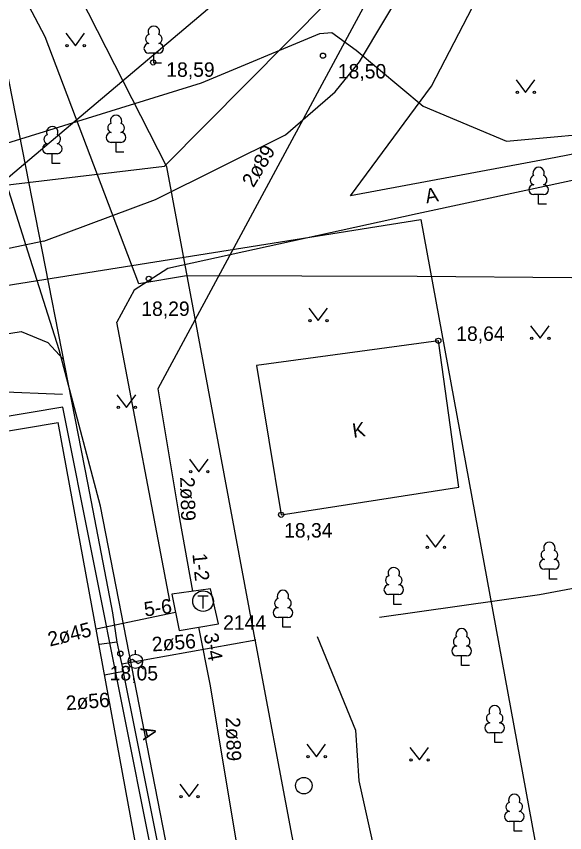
# Model space of a CAD drawing. Extents: x 713497 to 713863, y 6590062 to 6590327.
# Drawn here: x 713682.26 to 713708.83, y 6590102.5 to 6590142.1 of the extents above; entities that cross this region are included whole.
import ezdxf

# ---------------------------------------------------------------- set-up
doc = ezdxf.new("R2010")
doc.units = 0
for name, color, linetype in [('HALJASTUS', 7, 'Continuous'), ('HOONE', 7, 'Continuous'), ('HOONEDET', 7, 'Continuous'), ('KORGUS', 7, 'Continuous'), ('KTRASS', 7, 'Continuous'), ('MPKAABEL', 7, 'Continuous'), ('PUU', 7, 'Continuous'), ('SIKAEV', 7, 'Continuous'), ('SITRASS', 7, 'Continuous'), ('TEE', 7, 'Continuous'), ('TKAEV', 7, 'Continuous'), ('TORU NR', 7, 'Continuous'), ('TTRASS', 7, 'Continuous'), ('Слой 1', 7, 'Continuous')]:
    doc.layers.add(name, color=color, linetype=linetype)

msp = doc.modelspace()

# ---------------------------------------------------------------- linework, layer by layer
at = {"layer": 'HALJASTUS'}
for p, q in [((713684.657, 6590141.277), (713685.12, 6590140.67)), ((713685.12, 6590140.67), (713685.566, 6590141.277)), ((713706.477, 6590139.017), (713706.94, 6590138.41)), ((713706.94, 6590138.41), (713707.386, 6590139.017)), ((713696.427, 6590127.947), (713696.89, 6590127.34)), ((713696.89, 6590127.34), (713697.336, 6590127.947)), ((713707.177, 6590127.087), (713707.64, 6590126.48)), ((713707.64, 6590126.48), (713708.086, 6590127.087)), ((713687.137, 6590123.737), (713687.6, 6590123.13)), ((713687.6, 6590123.13), (713688.046, 6590123.737)), ((713690.647, 6590120.617), (713691.11, 6590120.01)), ((713691.11, 6590120.01), (713691.556, 6590120.617)), ((713702.117, 6590116.947), (713702.58, 6590116.34)), ((713702.58, 6590116.34), (713703.026, 6590116.947)), ((713696.337, 6590106.787), (713696.8, 6590106.18)), ((713696.8, 6590106.18), (713697.246, 6590106.787)), ((713701.327, 6590106.637), (713701.79, 6590106.03)), ((713701.79, 6590106.03), (713702.236, 6590106.637)), ((713690.177, 6590104.857), (713690.64, 6590104.25)), ((713690.64, 6590104.25), (713691.086, 6590104.857))]:
    msp.add_line(p, q, dxfattribs=at)
for points in [[(713712.88, 6590115.85), (713712.19, 6590114.89), (713707.62, 6590114.04), (713699.86, 6590112.93)], [(713696.83, 6590112.02), (713698.69, 6590107.47), (713698.85, 6590105.02), (713701.61, 6590092.64)]]:
    msp.add_lwpolyline(points, dxfattribs=at)
for centre, radius in [((713684.719, 6590140.67), 0.055), ((713685.548, 6590140.67), 0.055), ((713706.539, 6590138.41), 0.055), ((713707.368, 6590138.41), 0.055), ((713696.489, 6590127.34), 0.055), ((713697.318, 6590127.34), 0.055), ((713707.239, 6590126.48), 0.055), ((713708.068, 6590126.48), 0.055), ((713687.199, 6590123.13), 0.055), ((713688.028, 6590123.13), 0.055), ((713690.709, 6590120.01), 0.055), ((713691.538, 6590120.01), 0.055), ((713702.179, 6590116.34), 0.055), ((713703.008, 6590116.34), 0.055), ((713696.399, 6590106.18), 0.055), ((713697.228, 6590106.18), 0.055), ((713701.389, 6590106.03), 0.055), ((713702.218, 6590106.03), 0.055), ((713696.19, 6590104.78), 0.4), ((713690.239, 6590104.25), 0.055), ((713691.068, 6590104.25), 0.055)]:
    msp.add_circle(centre, radius, dxfattribs=at)
at = {"layer": 'HOONE'}
for p, q in [((713688.03, 6590111.16), (713688.03, 6590111.357)), ((713687.68, 6590110.808), (713687.891, 6590110.914)), ((713687.891, 6590110.914), (713688.169, 6590110.706)), ((713687.783, 6590110.563), (713687.643, 6590110.423)), ((713688.169, 6590110.706), (713688.38, 6590110.812)), ((713688.277, 6590110.563), (713688.417, 6590110.423))]:
    msp.add_line(p, q, dxfattribs=at)
for points in [[(713734.713, 6590179.152), (713722.026, 6590168.127), (713722.157, 6590168.056), (713711.65, 6590159.35), (713701.26, 6590150.68), (713673.462, 6590127.187), (713672.85, 6590126.67), (713647.99, 6590122.51), (713633.578, 6590120.32)], [(713693.84, 6590111.86), (713689.55, 6590134.79), (713682.39, 6590148.87), (713677.2, 6590159.52), (713676.53, 6590160.46), (713675.86, 6590163.24), (713675.04, 6590167.62)], [(713665.89, 6590132.03), (713669.505, 6590132.457), (713689.44, 6590134.83), (713709.36, 6590154.95), (713711.89, 6590153.81)], [(713693.89, 6590125.16), (713695.09, 6590117.91), (713703.71, 6590119.26), (713702.71, 6590126.36), (713693.89, 6590125.16)], [(713688.394, 6590100.066), (713671.828, 6590096.986), (713667.863, 6590119.623), (713684.288, 6590122.388)], [(713688.35, 6590100.23), (713684.288, 6590122.388)], [(713687.37, 6590110.69), (713693.86, 6590111.86)], [(713701.75, 6590069.87), (713695.62, 6590102.33), (713693.84, 6590111.87)]]:
    msp.add_lwpolyline(points, dxfattribs=at)
msp.add_circle((713688.03, 6590110.81), 0.35, dxfattribs=at)
at = {"layer": 'HOONEDET'}
for points in [[(713667.208, 6590120.227), (713671.415, 6590096.203), (713682.109, 6590098.012), (713685.75, 6590098.67), (713689.49, 6590099.42), (713688.82, 6590101.51), (713684.52, 6590123.14), (713667.208, 6590120.227)], [(713686.539, 6590110.153), (713687.45, 6590110.33), (713687.15, 6590111.74), (713686.268, 6590111.626)]]:
    msp.add_lwpolyline(points, dxfattribs=at)
at = {"layer": 'KORGUS'}
for centre in [(713697.12, 6590140.19), (713688.89, 6590139.86), (713688.68, 6590129.37), (713702.71, 6590126.36), (713695.09, 6590117.92), (713687.3, 6590111.18)]:
    msp.add_circle(centre, 0.125, dxfattribs=at)
at = {"layer": 'KTRASS'}
msp.add_line((713674.505, 6590124.158), (713684.495, 6590123.77), dxfattribs=at)
at = {"layer": 'MPKAABEL'}
for points in [[(713648.898, 6590189.999), (713650.232, 6590187.386), (713653.619, 6590186.331), (713654.135, 6590185.833), (713654.6, 6590184.884), (713659.445, 6590156.75), (713659.718, 6590154.881), (713660.539, 6590151.792), (713660.839, 6590151.655), (713663.967, 6590152.428), (713664.337, 6590151.977), (713669.307, 6590132.418), (713669.804, 6590132.227), (713691.237, 6590138.869), (713696.964, 6590141.27), (713697.553, 6590141.309), (713698.727, 6590140.465), (713701.978, 6590137.747), (713706.02, 6590136.037), (713711.684, 6590136.564)], [(713695.67, 6590069.59), (713692.27, 6590087.9), (713686.34, 6590118.33), (713684.33, 6590125.92), (713682.83, 6590130.66), (713676.1, 6590152.02), (713674.73, 6590155.85), (713674.34, 6590157.36), (713673.46, 6590161.22), (713670.72, 6590177.53), (713669.67, 6590183.54), (713667.81, 6590183.17)], [(713712.95, 6590130.05), (713709.16, 6590129.42), (713701.69, 6590129.47), (713690.5, 6590129.51), (713688.19, 6590129.12), (713683.66, 6590141.1), (713679.81, 6590148.4), (713679.37, 6590149.39), (713679.04, 6590150.26), (713678.83, 6590150.79), (713678.48, 6590151.44), (713677.98, 6590152.02), (713677.43, 6590152.31), (713676.95, 6590152.28), (713676.524, 6590152.014), (713670.183, 6590149.934), (713666.077, 6590148.723), (713655.565, 6590146.628), (713640.392, 6590143.766), (713637.411, 6590156.292), (713634.246, 6590158.892), (713632.822, 6590162.256), (713631.92, 6590167.25), (713628.288, 6590166.652)]]:
    msp.add_lwpolyline(points, dxfattribs=at)
at = {"layer": 'PUU'}
for p, q in [((713689.16, 6590140.305), (713688.68, 6590140.305)), ((713688.92, 6590139.83), (713688.92, 6590140.305)), ((713689.3, 6590139.83), (713688.92, 6590139.83)), ((713687.33, 6590135.985), (713686.85, 6590135.985)), ((713687.09, 6590135.51), (713687.09, 6590135.985)), ((713684.24, 6590135.435), (713683.76, 6590135.435)), ((713684, 6590134.96), (713684, 6590135.435)), ((713687.47, 6590135.51), (713687.09, 6590135.51)), ((713684.38, 6590134.96), (713684, 6590134.96)), ((713707.81, 6590133.455), (713707.33, 6590133.455)), ((713707.57, 6590132.98), (713707.57, 6590133.455)), ((713707.95, 6590132.98), (713707.57, 6590132.98)), ((713708.33, 6590115.275), (713707.85, 6590115.275)), ((713708.09, 6590114.8), (713708.09, 6590115.275)), ((713708.47, 6590114.8), (713708.09, 6590114.8)), ((713700.79, 6590114.045), (713700.31, 6590114.045)), ((713700.55, 6590113.57), (713700.55, 6590114.045)), ((713700.93, 6590113.57), (713700.55, 6590113.57)), ((713695.42, 6590112.935), (713694.94, 6590112.935)), ((713695.18, 6590112.46), (713695.18, 6590112.935)), ((713695.56, 6590112.46), (713695.18, 6590112.46)), ((713704.08, 6590111.075), (713703.6, 6590111.075)), ((713703.84, 6590110.6), (713703.84, 6590111.075)), ((713704.22, 6590110.6), (713703.84, 6590110.6)), ((713705.68, 6590107.345), (713705.2, 6590107.345)), ((713705.44, 6590106.87), (713705.44, 6590107.345)), ((713705.82, 6590106.87), (713705.44, 6590106.87)), ((713706.63, 6590103.045), (713706.15, 6590103.045)), ((713706.39, 6590102.57), (713706.39, 6590103.045)), ((713706.77, 6590102.57), (713706.39, 6590102.57))]:
    msp.add_line(p, q, dxfattribs=at)
for centre, radius, start, end in [((713688.92, 6590141.35), 0.277, 332.5799, 207.4201), ((713688.75, 6590141.003), 0.233, 109.0217, 253.1415), ((713689.09, 6590141.003), 0.233, 286.8508, 70.9859), ((713688.683, 6590140.542), 0.238, 90.0016, 269.3953), ((713689.157, 6590140.542), 0.238, 270.6047, 89.9984), ((713687.09, 6590137.03), 0.277, 332.5799, 207.4201), ((713684, 6590136.48), 0.277, 332.5799, 207.4201), ((713686.92, 6590136.683), 0.233, 109.0217, 253.1415), ((713687.26, 6590136.683), 0.233, 286.8508, 70.9859), ((713683.83, 6590136.133), 0.233, 109.0217, 253.1415), ((713684.17, 6590136.133), 0.233, 286.8508, 70.9859), ((713686.853, 6590136.222), 0.238, 90.0016, 269.3953), ((713687.327, 6590136.222), 0.238, 270.6047, 89.9984), ((713683.763, 6590135.672), 0.238, 90.0016, 269.3953), ((713684.237, 6590135.672), 0.238, 270.6047, 89.9984), ((713707.57, 6590134.5), 0.277, 332.5799, 207.4201), ((713707.4, 6590134.153), 0.233, 109.0217, 253.1415), ((713707.74, 6590134.153), 0.233, 286.8508, 70.9859), ((713707.333, 6590133.692), 0.238, 90.0016, 269.3953), ((713707.807, 6590133.692), 0.238, 270.6047, 89.9984), ((713708.09, 6590116.32), 0.277, 332.5799, 207.4201), ((713707.92, 6590115.973), 0.233, 109.0217, 253.1415), ((713708.26, 6590115.973), 0.233, 286.8508, 70.9859), ((713707.853, 6590115.512), 0.238, 90.0016, 269.3953), ((713708.327, 6590115.512), 0.238, 270.6047, 89.9984), ((713700.55, 6590115.09), 0.277, 332.5799, 207.4201), ((713700.38, 6590114.743), 0.233, 109.0217, 253.1415), ((713700.72, 6590114.743), 0.233, 286.8508, 70.9859), ((713700.313, 6590114.282), 0.238, 90.0016, 269.3953), ((713700.787, 6590114.282), 0.238, 270.6047, 89.9984), ((713695.18, 6590113.98), 0.277, 332.5799, 207.4201), ((713695.01, 6590113.633), 0.233, 109.0217, 253.1415), ((713695.35, 6590113.633), 0.233, 286.8508, 70.9859), ((713694.943, 6590113.172), 0.238, 90.0016, 269.3953), ((713695.417, 6590113.172), 0.238, 270.6047, 89.9984), ((713703.84, 6590112.12), 0.277, 332.5799, 207.4201), ((713703.67, 6590111.773), 0.233, 109.0217, 253.1415), ((713704.01, 6590111.773), 0.233, 286.8508, 70.9859), ((713703.603, 6590111.312), 0.238, 90.0016, 269.3953), ((713704.077, 6590111.312), 0.238, 270.6047, 89.9984), ((713705.44, 6590108.39), 0.277, 332.5799, 207.4201), ((713705.27, 6590108.043), 0.233, 109.0217, 253.1415), ((713705.61, 6590108.043), 0.233, 286.8508, 70.9859), ((713705.203, 6590107.582), 0.238, 90.0016, 269.3953), ((713705.677, 6590107.582), 0.238, 270.6047, 89.9984), ((713706.39, 6590104.09), 0.277, 332.5799, 207.4201), ((713706.22, 6590103.743), 0.233, 109.0217, 253.1415), ((713706.56, 6590103.743), 0.233, 286.8508, 70.9859), ((713706.153, 6590103.282), 0.238, 90.0016, 269.3953), ((713706.627, 6590103.282), 0.238, 270.6047, 89.9984)]:
    msp.add_arc(centre, radius, start, end, dxfattribs=at)
at = {"layer": 'SITRASS'}
for points in [[(713687.14, 6590111.74), (713686.93, 6590113.16), (713685.74, 6590119.38), (713681.26, 6590142.15), (713679.44, 6590151.52), (713678.67, 6590155.09), (713678.3, 6590158.03), (713677.24, 6590164.66), (713675.61, 6590175.98), (713675.04, 6590179.17), (713674.81, 6590179.63)], [(713695.14, 6590069.57), (713691.85, 6590087.49), (713690.14, 6590096.87), (713688.09, 6590107.14), (713687.42, 6590110.45)]]:
    msp.add_lwpolyline(points, dxfattribs=at)
at = {"layer": 'TEE'}
for points in [[(713683.592, 6590131.191), (713688.999, 6590133.216), (713695.297, 6590136.355), (713697.706, 6590138.431), (713698.882, 6590139.89), (713703.752, 6590148.044), (713706.695, 6590154.617), (713706.66, 6590155.945), (713704.814, 6590160.277), (713701.769, 6590163.764), (713698.347, 6590166.794), (713694.482, 6590170.539)], [(713708.411, 6590135.253), (713698.461, 6590133.384), (713702.375, 6590138.709), (713709.41, 6590152.273), (713712.047, 6590135.954), (713708.411, 6590135.253)], [(713724.118, 6590062.302), (713723.44, 6590065.38), (713721.87, 6590070.76), (713721.55, 6590072.92), (713716.91, 6590102.31), (713714.19, 6590119.04), (713713.21, 6590127.08), (713712.97, 6590129.65), (713712.223, 6590134.78), (713701.682, 6590132.514), (713689.607, 6590129.871), (713687.975, 6590128.819), (713687.123, 6590127.269)], [(713683.592, 6590131.191), (713663.747, 6590127.042)], [(713689.691, 6590113.741), (713687.123, 6590127.269)], [(713664.384, 6590123.896), (713682.485, 6590126.805), (713683.778, 6590126.282), (713684.525, 6590125.47)]]:
    msp.add_lwpolyline(points, dxfattribs=at)
at = {"layer": 'TKAEV'}
for p, q in [((713691.06, 6590113.98), (713691.56, 6590113.98)), ((713691.31, 6590113.38), (713691.31, 6590113.98))]:
    msp.add_line(p, q, dxfattribs=at)
msp.add_circle((713691.31, 6590113.73), 0.5, dxfattribs=at)
at = {"layer": 'TTRASS'}
for points in [[(713708.24, 6590159.57), (713689.12, 6590124.03), (713690.17, 6590117.72), (713690.8, 6590114.21)], [(713689.8, 6590114.07), (713690.15, 6590112.3), (713692.06, 6590112.63), (713691.67, 6590114.33), (713689.8, 6590114.07)], [(713689.98, 6590113.18), (713686.124, 6590112.371)], [(713691.09, 6590112.46), (713691.65, 6590109.62), (713698.29, 6590069.71)]]:
    msp.add_lwpolyline(points, dxfattribs=at)
at = {"layer": 'Слой 1'}
msp.add_lwpolyline([(713701.86, 6590132.24), (713709.27, 6590091.83), (713671.83, 6590085.15), (713664.19, 6590126.25)], close=True, dxfattribs=at)

# ---------------------------------------------------------------- texts
at = {"layer": 'HOONE'}
msp.add_text('K', height=0.7, rotation=8.4049, dxfattribs=at).set_placement((713698.597, 6590121.648))
at = {"layer": 'KORGUS'}
for s, p in [('18,59', (713689.526, 6590139.165)), ('18,50', (713697.841, 6590139.085)), ('18,29', (713688.316, 6590127.565)), ('18,64', (713703.578, 6590126.355)), ('18,34', (713695.238, 6590116.815)), ('18,05', (713686.783, 6590109.885))]:
    msp.add_text(s, height=0.7, dxfattribs=at).set_placement(p)
at = {"layer": 'SIKAEV'}
msp.add_text('2144', height=0.7, dxfattribs=at).set_placement((713692.28, 6590112.34))
at = {"layer": 'TEE'}
for rotation, p in [(10.3566, (713702.137, 6590133.022)), (283.9574, (713688.262, 6590107.563))]:
    msp.add_text('A', height=0.7, rotation=rotation, dxfattribs=at).set_placement(p)
at = {"layer": 'TORU NR'}
for s, rotation, p in [('2ø89', 59.3381, (713693.749, 6590133.753)), ('2ø89', 271.4911, (713690.196, 6590119.743)), ('1-2', 275.6924, (713690.791, 6590116.02)), ('5-6', 7.6287, (713688.493, 6590112.981)), ('2ø45', 14.1951, (713683.883, 6590111.523)), ('2ø56', 4.6236, (713688.857, 6590111.285)), ('3-4', 280.8525, (713691.332, 6590112.111)), ('2ø56', 4.6236, (713684.687, 6590108.435)), ('2ø89', 271.4911, (713692.406, 6590108.093))]:
    msp.add_text(s, height=0.7, rotation=rotation, dxfattribs=at).set_placement(p)

doc.saveas('drawing.dxf')
